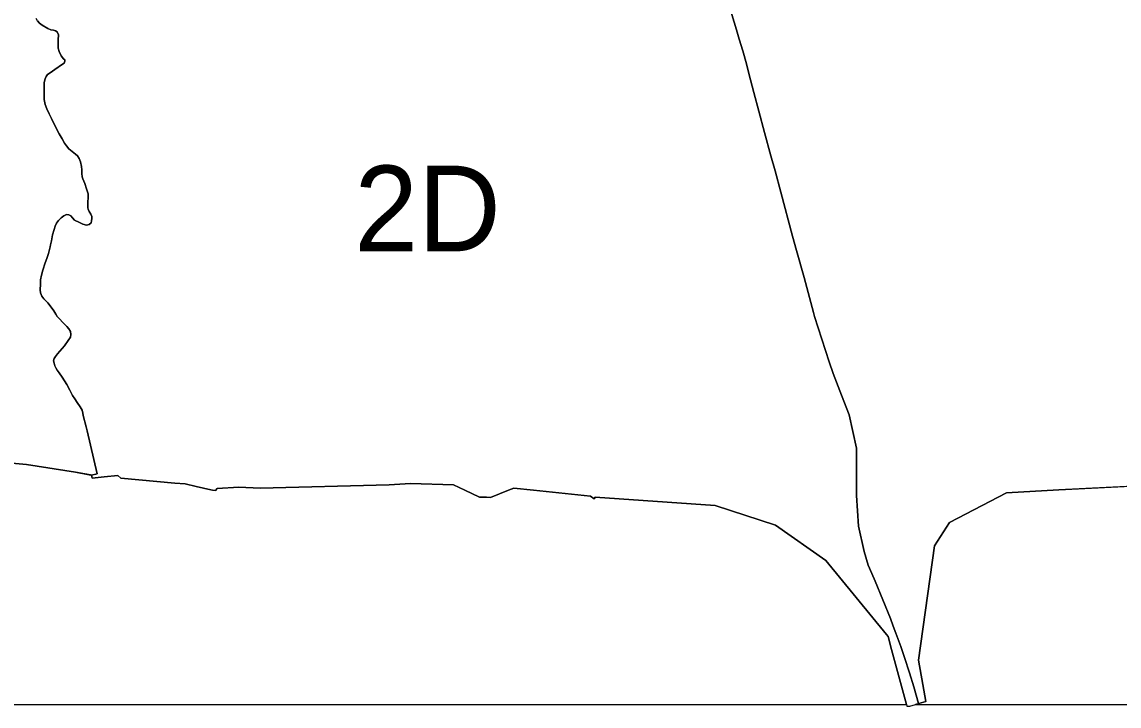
# Model space of a CAD drawing. Extents: x 152750 to 166250, y 378996 to 390000.
# Drawn here: x 161080 to 163640, y 378996 to 380593 of the extents above; entities that cross this region are included whole.
import ezdxf

# ---------------------------------------------------------------- set-up
doc = ezdxf.new("R2010")
doc.units = 0
doc.layers.add('BLT_Nummers', color=7, linetype='Continuous')
doc.layers.add('BLT_Shapes', color=7, linetype='Continuous')

msp = doc.modelspace()

# ---------------------------------------------------------------- linework, layer by layer
at = {"layer": 'BLT_Shapes'}
for p, q in [((161140, 380577.6), (161126.9, 380585.3)), ((161147.6, 380574.8), (161140, 380577.6)), ((161161.8, 380569.7), (161158.1, 380572.2)), ((161176.5, 380507.2), (161171.4, 380513.8)), ((161136.1, 380465.7), (161139.7, 380469.9)), ((161134.3, 380400.6), (161131.7, 380411.8)), ((162813.1, 380335.1), (162827.9, 380280.5)), ((161216.2, 380266.5), (161213.5, 380274.4)), ((161218.7, 380255.6), (161216.2, 380266.5)), ((162827.9, 380280.5), (162837.4, 380245.3)), ((161221.8, 380226.5), (161220.1, 380231.7)), ((161234.1, 380191.9), (161230.8, 380203.6)), ((161234.8, 380182.4), (161234.1, 380191.9)), ((161234.3, 380155.7), (161233.7, 380158.7)), ((161154.8, 380108.6), (161157.7, 380116.5)), ((161157.7, 380116.5), (161160.5, 380123)), ((161160.5, 380123), (161165.5, 380129.7)), ((161165.5, 380129.7), (161171.4, 380135.8)), ((161197.5, 380135.4), (161202.2, 380130.6)), ((161148.9, 380082.3), (161151.2, 380096)), ((161151.2, 380096), (161154.8, 380108.6)), ((161146.8, 380072.7), (161148.9, 380082.3)), ((162887.9, 380059.8), (162905.6, 379996.6)), ((162905.6, 379996.6), (162927.1, 379914.8)), ((161122.4, 379967.8), (161122.9, 379981.2)), ((161140.4, 379937.3), (161135.7, 379941.9)), ((161145.6, 379930.7), (161140.4, 379937.3)), ((162927.1, 379914.8), (162929.6, 379905.7)), ((161166.6, 379900.6), (161162.2, 379905.6)), ((161193.3, 379870.5), (161189.4, 379876.9)), ((161163.2, 379818.6), (161178.8, 379837)), ((161229.6, 379647.8), (161223.1, 379674.2)), ((163010.8, 379675.6), (163027.4, 379597.8)), ((163027.4, 379597.8), (163027.6, 379488)), ((161204.6, 379542), (161236.8, 379536.2)), ((161236.8, 379536.2), (161239.7, 379535.7)), ((161239.7, 379535.7), (161242.5, 379535.2)), ((161242.5, 379535.2), (161255.8, 379538.2)), ((161257.5, 379529.8), (161271.9, 379531.1)), ((161531.7, 379499.1), (161535.7, 379504.3)), ((161936.6, 379512.9), (161986.7, 379515.5)), ((161986.7, 379515.5), (162086.7, 379512.8)), ((162086.7, 379512.8), (162113.8, 379500)), ((162215.4, 379500), (162227.5, 379504.9)), ((163500, 379501.2), (163783.7, 379515.1)), ((163172.1, 379103.2), (163209.7, 379370.2)), ((163071.1, 379287.9), (163106.7, 379200.8)), ((163106.7, 379200.8), (163113.5, 379183)), ((163113.5, 379183), (163119.6, 379166.7)), ((163109.5, 379128.5), (163144.2, 379000)), ((163182.3, 379046.7), (163172.1, 379103.2)), ((163189.5, 379006.8), (163182.3, 379046.7)), ((163144.2, 379000), (163145.3, 378996.2)), ((163145.3, 378996.2), (163151.8, 378996.2)), ((163151.8, 378996.2), (163165.3, 379000)), ((163165.3, 379000), (163172.4, 379002)), ((163172.4, 379002), (163173.2, 379002.2)), ((163173.2, 379002.2), (163189.5, 379006.8))]:
    msp.add_line(p, q, dxfattribs=at)
for points in [[(162672.9, 380798.7), (162693.5, 380731.2), (162697.6, 380720.1), (162736.7, 380610.5), (162747.6, 380574.5)], [(161126.9, 380585.3), (161121.2, 380589.8), (161116.4, 380595.2), (161113, 380600.6)], [(163172.4, 379002), (163161.1, 379040.9), (163151.3, 379073.5), (163139.6, 379109.5), (163130.7, 379135.6), (163119.6, 379166.7), (163113.5, 379183), (163106.7, 379200.8), (163071.1, 379287.9), (163063.1, 379305.7), (163054.8, 379325.1), (163045.3, 379357.3), (163032, 379416.1), (163027.6, 379488), (163027.4, 379597.8), (163010.8, 379675.6), (162992.5, 379722), (162973.5, 379772.8), (162964.2, 379799.7), (162929.6, 379905.7), (162927.1, 379914.8), (162905.6, 379996.6), (162887.9, 380059.8), (162878.4, 380092.6), (162850.7, 380195.3), (162837.4, 380245.3), (162827.9, 380280.5), (162813.1, 380335.1), (162800, 380384.4), (162788.3, 380428.3), (162776.3, 380472.4), (162770.5, 380495.2), (162762.2, 380525.8), (162754.1, 380553.1), (162747.6, 380574.5), (162736.7, 380610.5)], [(161116.4, 380595.2), (161121.2, 380589.8), (161126.9, 380585.3), (161140, 380577.6), (161147.6, 380574.8), (161153.6, 380573.4), (161158.1, 380572.2), (161161.8, 380569.7), (161165.2, 380563.1), (161164.6, 380551.5), (161164.1, 380541.6), (161164.1, 380531.6), (161166.9, 380523.7), (161171.4, 380513.8), (161176.5, 380507.2), (161179.7, 380504.4), (161180.2, 380501.6), (161178.1, 380497), (161174.7, 380494.3), (161156.3, 380481.8), (161145.6, 380474.5), (161139.7, 380469.9), (161136.1, 380465.7), (161133.7, 380460), (161131.9, 380451.6), (161131.7, 380429.2), (161131.7, 380411.8), (161134.3, 380400.6)], [(161158.1, 380572.2), (161153.6, 380573.4), (161147.6, 380574.8)], [(162747.6, 380574.5), (162754.1, 380553.1), (162762.2, 380525.8)], [(161164.6, 380551.5), (161165.2, 380563.1), (161161.8, 380569.7)], [(161164.1, 380531.6), (161164.1, 380541.6), (161164.6, 380551.5)], [(161171.4, 380513.8), (161166.9, 380523.7), (161164.1, 380531.6)], [(162762.2, 380525.8), (162770.5, 380495.2), (162776.3, 380472.4)], [(161174.7, 380494.3), (161178.1, 380497), (161180.2, 380501.6)], [(161180.2, 380501.6), (161179.7, 380504.4), (161176.5, 380507.2)], [(161139.7, 380469.9), (161145.6, 380474.5), (161156.3, 380481.8), (161174.7, 380494.3)], [(162776.3, 380472.4), (162788.3, 380428.3), (162800, 380384.4), (162813.1, 380335.1)], [(161131.7, 380411.8), (161131.7, 380429.2), (161131.9, 380451.6), (161133.7, 380460), (161136.1, 380465.7)], [(161134.3, 380400.6), (161138.1, 380390.1), (161143.2, 380378.1), (161148.6, 380367.4), (161158.1, 380348.2), (161167, 380332), (161173.7, 380320.1), (161179.4, 380310.2), (161183.5, 380304.1), (161189.3, 380297.1), (161196.8, 380290.5), (161205, 380284.1), (161209.9, 380280.1), (161213.5, 380274.4), (161216.2, 380266.5), (161218.7, 380255.6), (161219.6, 380247.8), (161219.8, 380239), (161220.1, 380231.7), (161221.8, 380226.5), (161226.6, 380215.7), (161230.8, 380203.6), (161234.1, 380191.9), (161234.8, 380182.4), (161234, 380173.3), (161233.5, 380164.6), (161233.7, 380158.7), (161234.3, 380155.7), (161236.9, 380150.3), (161240.8, 380144), (161242.9, 380139.1), (161243, 380134.1), (161242.5, 380128.6), (161241.1, 380124.3), (161236.5, 380120.2), (161230.8, 380118.9), (161222.1, 380120.6), (161214.1, 380124.5), (161202.2, 380130.6), (161197.5, 380135.4), (161194.3, 380140.1), (161189.6, 380142.9), (161184.1, 380143.5), (161177.5, 380140.6), (161171.4, 380135.8), (161165.5, 380129.7), (161160.5, 380123), (161157.7, 380116.5), (161154.8, 380108.6), (161151.2, 380096), (161148.9, 380082.3), (161146.8, 380072.7), (161145.6, 380067.7), (161141.5, 380052.4), (161138, 380040.6), (161134.1, 380030.5), (161128.5, 380013.7), (161125.2, 380001.7), (161123.4, 379991.4), (161122.9, 379981.2), (161122.4, 379967.8), (161123.5, 379961), (161126.2, 379952.7), (161130.6, 379946.7), (161135.7, 379941.9), (161140.4, 379937.3), (161145.6, 379930.7), (161154.1, 379918.3), (161158.7, 379910.7), (161162.2, 379905.6), (161166.6, 379900.6), (161176.3, 379890.4), (161184.6, 379882.4), (161189.4, 379876.9), (161193.3, 379870.5), (161194, 379863.8), (161192.8, 379857.5), (161187.9, 379849.8), (161178.8, 379837), (161163.2, 379818.6), (161157.9, 379812.2), (161154.8, 379807.2), (161153.8, 379802), (161154.8, 379796.7), (161156.3, 379790.2), (161158.6, 379785.5), (161162.1, 379780.3), (161167.1, 379773.9), (161173.9, 379764.2), (161184.3, 379747.1), (161191.6, 379733.2), (161197.6, 379720.8), (161203, 379713), (161208.4, 379704.9), (161215.9, 379694.4), (161220.1, 379686.9), (161221.7, 379679.5), (161223.1, 379674.2), (161229.6, 379647.8), (161231.8, 379638.3), (161255.8, 379538.2), (161242.5, 379535.2)], [(161173.7, 380320.1), (161167, 380332), (161158.1, 380348.2), (161148.6, 380367.4), (161143.2, 380378.1), (161138.1, 380390.1), (161134.3, 380400.6)], [(161189.3, 380297.1), (161183.5, 380304.1), (161179.4, 380310.2), (161173.7, 380320.1)], [(161213.5, 380274.4), (161209.9, 380280.1), (161205, 380284.1), (161196.8, 380290.5), (161189.3, 380297.1)], [(161220.1, 380231.7), (161219.8, 380239), (161219.6, 380247.8), (161218.7, 380255.6)], [(162837.4, 380245.3), (162850.7, 380195.3), (162878.4, 380092.6), (162887.9, 380059.8)], [(161230.8, 380203.6), (161226.6, 380215.7), (161221.8, 380226.5)], [(161233.7, 380158.7), (161233.5, 380164.6), (161234, 380173.3), (161234.8, 380182.4)], [(161171.4, 380135.8), (161177.5, 380140.6), (161184.1, 380143.5), (161189.6, 380142.9)], [(161189.6, 380142.9), (161194.3, 380140.1), (161197.5, 380135.4)], [(161242.9, 380139.1), (161240.8, 380144), (161236.9, 380150.3), (161234.3, 380155.7)], [(161241.1, 380124.3), (161242.5, 380128.6), (161243, 380134.1), (161242.9, 380139.1)], [(161202.2, 380130.6), (161214.1, 380124.5), (161222.1, 380120.6), (161230.8, 380118.9), (161236.5, 380120.2), (161241.1, 380124.3)], [(161138, 380040.6), (161141.5, 380052.4), (161145.6, 380067.7), (161146.8, 380072.7)], [(161122.9, 379981.2), (161123.4, 379991.4), (161125.2, 380001.7), (161128.5, 380013.7), (161134.1, 380030.5), (161138, 380040.6)], [(161126.2, 379952.7), (161123.5, 379961), (161122.4, 379967.8)], [(161135.7, 379941.9), (161130.6, 379946.7), (161126.2, 379952.7)], [(161162.2, 379905.6), (161158.7, 379910.7), (161154.1, 379918.3), (161145.6, 379930.7)], [(161189.4, 379876.9), (161184.6, 379882.4), (161176.3, 379890.4), (161166.6, 379900.6)], [(162929.6, 379905.7), (162964.2, 379799.7), (162973.5, 379772.8), (162992.5, 379722), (163010.8, 379675.6)], [(161178.8, 379837), (161187.9, 379849.8), (161192.8, 379857.5), (161194, 379863.8), (161193.3, 379870.5)], [(161156.3, 379790.2), (161154.8, 379796.7), (161153.8, 379802), (161154.8, 379807.2)], [(161154.8, 379807.2), (161157.9, 379812.2), (161163.2, 379818.6)], [(161167.1, 379773.9), (161162.1, 379780.3), (161158.6, 379785.5), (161156.3, 379790.2)], [(161184.3, 379747.1), (161173.9, 379764.2), (161167.1, 379773.9)], [(161208.4, 379704.9), (161203, 379713), (161197.6, 379720.8), (161191.6, 379733.2), (161184.3, 379747.1)], [(161223.1, 379674.2), (161221.7, 379679.5), (161220.1, 379686.9), (161215.9, 379694.4), (161208.4, 379704.9)], [(161255.8, 379538.2), (161231.8, 379638.3), (161229.6, 379647.8)], [(157972.7, 379000), (163144.2, 379000), (163109.5, 379128.5), (163101.2, 379158.8), (163097.8, 379163.1), (162956.1, 379336), (162838.9, 379418.6), (162697.7, 379464), (162417.8, 379483.9), (162415.1, 379479.8), (162406.7, 379486), (162273.5, 379500.1), (162227.5, 379504.9), (162215.4, 379500), (162173.2, 379483.1), (162164, 379483.4), (162155.6, 379483.7), (162149, 379484), (162147.5, 379484), (162113.8, 379500), (162086.7, 379512.8), (161986.7, 379515.5), (161936.6, 379512.9), (161635.7, 379504.6), (161585.8, 379507.3), (161535.7, 379504.3), (161531.7, 379499.1), (161524.4, 379500), (161521, 379500.8), (161486.1, 379508.8), (161461.1, 379514.6), (161436.7, 379516.8), (161310.5, 379528.5), (161303.5, 379534.1), (161271.9, 379531.1), (161257.5, 379529.8), (161243.4, 379528.5), (161242.5, 379535.2), (161239.7, 379535.7), (161204.6, 379542), (161090.1, 379559.8), (161021.4, 379566.4)], [(161021.4, 379566.4), (161090.1, 379559.8), (161204.6, 379542)], [(161242.5, 379535.2), (161243.4, 379528.5), (161257.5, 379529.8)], [(161271.9, 379531.1), (161303.5, 379534.1), (161310.5, 379528.5), (161436.7, 379516.8)], [(161436.7, 379516.8), (161461.1, 379514.6), (161486.1, 379508.8), (161521, 379500.8), (161524.4, 379500), (161531.7, 379499.1)], [(161535.7, 379504.3), (161585.8, 379507.3), (161635.7, 379504.6), (161936.6, 379512.9)], [(162113.8, 379500), (162147.5, 379484), (162149, 379484)], [(162164, 379483.4), (162173.2, 379483.1), (162215.4, 379500)], [(162227.5, 379504.9), (162273.5, 379500.1), (162406.7, 379486), (162415.1, 379479.8)], [(163783.7, 379515.1), (163500, 379501.2), (163378, 379494), (163244.6, 379425), (163209.7, 379370.2), (163172.1, 379103.2), (163182.3, 379046.7), (163189.5, 379006.8), (163173.2, 379002.2), (163165.3, 379000), (166250, 379000)], [(163209.7, 379370.2), (163244.6, 379425), (163378, 379494), (163500, 379501.2)], [(162149, 379484), (162155.6, 379483.7), (162164, 379483.4)], [(162415.1, 379479.8), (162417.8, 379483.9), (162697.7, 379464), (162838.9, 379418.6)], [(163027.6, 379488), (163032, 379416.1), (163045.3, 379357.3), (163054.8, 379325.1), (163063.1, 379305.7), (163071.1, 379287.9)], [(162838.9, 379418.6), (162956.1, 379336), (163097.8, 379163.1)], [(163119.6, 379166.7), (163130.7, 379135.6), (163139.6, 379109.5)], [(163097.8, 379163.1), (163101.2, 379158.8), (163109.5, 379128.5)], [(163139.6, 379109.5), (163151.3, 379073.5), (163161.1, 379040.9), (163172.4, 379002)], [(163144.2, 379000), (163144.2, 379000)]]:
    msp.add_lwpolyline(points, dxfattribs=at)

# ---------------------------------------------------------------- texts
at = {"layer": 'BLT_Nummers'}
msp.add_text('2D', height=200, dxfattribs=at).set_placement((161855.5, 380057.6))

doc.saveas('drawing.dxf')
